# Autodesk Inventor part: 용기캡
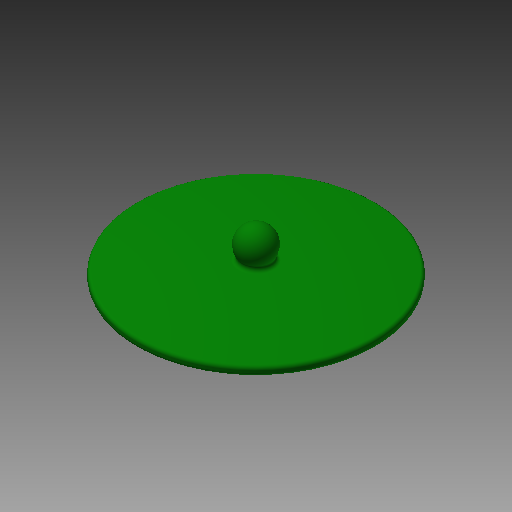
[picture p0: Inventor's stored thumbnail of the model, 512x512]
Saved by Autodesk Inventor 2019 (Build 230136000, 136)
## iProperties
Created: 2018-01
Part Number: 용기캡
Material: ABS 플라스틱
Document SubType Name: Modeling
Designer: mduedu
Density: 1 g/cm^3
Appearance: 진녹색
Author: mduedu
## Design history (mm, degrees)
sketch "스케치1"
  geometry: L1 (-35, 2.5)-(0, 2.5); L2 (0, 5)-(0, 0); L3 (0, 0)-(-35, 0); L4 (-35, 0)-(-35, 2.5); L5 (-31, 0)-(-29, 0); L6 (-29, 0)-(-29, -2); L7 (-29, -2)-(-31, -2); L8 (-31, -2)-(-31, 0); A1 r 246.25 centre (0, -241.25) between (0, 5) and (-35, 2.5); 1 further point
  constraints: 16 end point, 4 parallel, 2 horizontal, 2 perpendicular, 2 point on circle, 1 centre point, 1 coincident, 1 midpoint, 1 point on line, 1 vertical alignment
  dimensions: "d2" = 70 diameter of L4 L2; "d3" = 5 distance from line of L2.start L3; "d4" = 2.5 distance of L3.end L1.start; "d5" = 4 distance between parallel lines of L8 L4; "d6" = 2 distance of L6.end L7.end; "d7" = 2 distance between parallel lines of L7 L3
revolve "회전1" sketch "스케치1" stored, may be unused: angle "d8" = 90 deg
chamfer "모따기1" distance "d9" = 0.5; stored, may be unused: second distance "d10" = 2, angle "d11" = 45 deg
fillet "모깎기1" dims "d12" = 1
fillet "모깎기2" dims "d13" = 1
sketch "스케치2"
  geometry: L1 (-30.5, -2)-(-31, -1.5) reference; L2 (-31, -1.5)-(-31, 0) reference; L3 (-31, 0)-(-34, 0) reference; L4 (-35, 1)-(-35, 1.632) reference; L5 (35, 1.632)-(35, 1) reference; L6 (34, 0)-(31, 0) reference; L7 (31, 0)-(31, -1.5) reference; L8 (31, -1.5)-(30.5, -2) reference; L9 (30.5, -2)-(29, -2) reference; L10 (29, -2)-(29, -1) reference; L11 (28, 0)-(-28, 0) reference; L12 (-29, -1)-(-29, -2) reference; L13 (-29, -2)-(-30.5, -2) reference; L14 (0, 14)-(0, 4); A1 r 1 centre (-34, 1) between (-35, 1) and (-34, 0) reference; A2 r 1 centre (-34, 1.632) between (-34.139, 2.622) and (-35, 1.632) reference; A3 r 246.25 centre (0, -241.25) between (34.139, 2.622) and (-34.139, 2.622) reference; A4 r 1 centre (34, 1.632) between (35, 1.632) and (34.139, 2.622) reference; A5 r 1 centre (34, 1) between (34, 0) and (35, 1) reference; A6 r 1 centre (28, -1) between (29, -1) and (28, 0) reference; A7 r 1 centre (-28, -1) between (-28, 0) and (-29, -1) reference; A8 r 5 centre (0, 9) between (0, 14) and (0, 4); 3 further points
  constraints: 2 end point, 2 midpoint, 2 point on circle, 1 centre point, 1 coincident, 1 perpendicular, 1 point on line, 1 vertical alignment
  dimensions: "d14" = 10 diameter of A8; "d16" = 9 distance of A8.centre point (0, 0)
revolve "회전2" sketch "스케치2" stored, may be unused: angle "d17" = 90 deg
fillet "모깎기3" dims "d18" = 1
node "솔리드1"
node "절단 모서리 투영1"
